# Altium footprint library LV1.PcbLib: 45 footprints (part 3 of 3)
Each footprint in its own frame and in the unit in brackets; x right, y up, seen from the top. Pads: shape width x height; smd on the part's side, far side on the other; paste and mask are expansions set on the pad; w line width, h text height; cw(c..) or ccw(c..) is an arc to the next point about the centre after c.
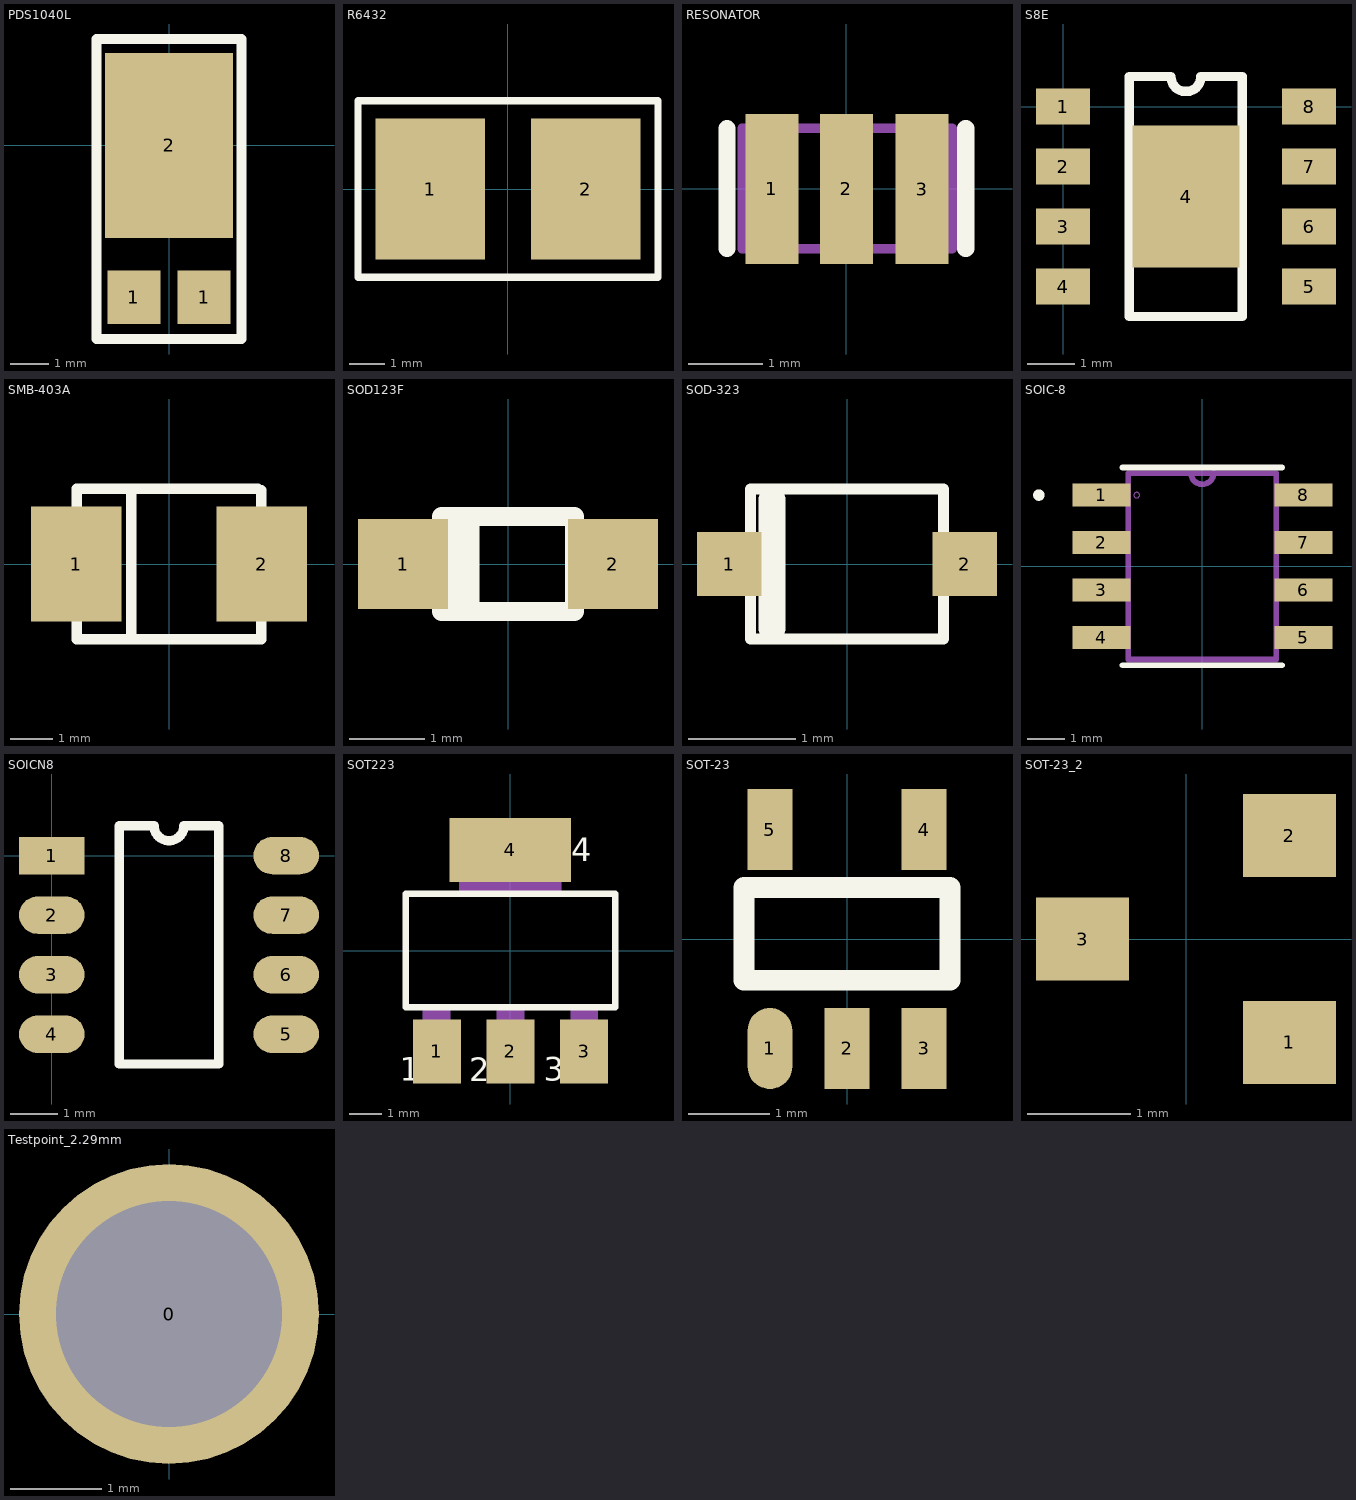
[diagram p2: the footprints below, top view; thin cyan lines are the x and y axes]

## PDS1040L [mm]
height 7.12
pads (3):
  rect 1.39x1.4 smd: 1(-0.92,-3.982) 1(0.92,-3.982)
  rect 3.36x4.86 smd: 2(0,0)
Top Overlay:
  lines w0.254: -1.905,-5.08 1.905,-5.08 1.905,2.794 -1.905,2.794 -1.905,-5.08
3D body: height 0.1, standoff 0, extent -1.397,0.762 1.397,2.286
3D body: height 0.1, standoff 0, extent -1.397,-4.064 -0.381,-2.032
3D body: height 0.1, standoff 0, extent 0.381,-4.064 1.397,-2.032
3D body: height 1, standoff 0, extent -1.524,-3.429 1.524,1.524

## R6432 [mm]
height 7.12
pads (2):
  rect 3.1x4 smd: 1(-2.2,0) 2(2.2,0)
Top Overlay:
  lines w0.2: -4.25,-2.5 -4.25,0 -4.25,2.5 4.25,2.5 4.25,-2.5 -4.25,-2.5

## RESONATOR [mil]
height 338.58
pads (3):
  rect 28x79 smd: 1(-39.37,0) 2(0,0) 3(40,0)
Top Overlay:
  lines w9: -62.99,-31.5 -62.99,32 ; 63,-31.5 63,32
Mechanical 16:
  lines w5: -55.12,-31.5 -55.12,32 56,32 56,-31.5 -55.12,-31.5

## S8E [mil]
height 338.58
pads (9):
  rect 45x30 smd: 1(0,0) 2(0,-50) 3(0,-100) 4(0,-150) 5(205,-150) 6(205,-100) 7(205,-50) 8(205,0)
  rect 89x118 smd: 4(102.5,-75)
Top Overlay:
  lines w7.87: 55.37,-175 149.47,-175 149.47,25 114.92,25 cw(c102.42,25) 89.92,25 55.37,25 55.37,-175

## SMB-403A [mil]
pads (2):
  rect 85x107.99 smd: 1(-87.01,0) 2(87.01,0)
Top Overlay:
  lines w10: -86.61,-70.87 -86.61,69.29 ; -86.61,70.87 83.46,70.87 ; -83.46,-70.87 86.61,-70.87 86.61,69.29 ; -35.43,-70.87 -35.43,70.87
3D body: height 78.74, standoff 0, extent -82.68,-74.8 90.55,66.93

## SOD123F [mm]
height 7.12
pads (2):
  rect 1.2x1.2 smd: 1(-1.4,0) 2(1.4,0)
Top Overlay:
  rectangle: -1.016,-0.635 -0.381,0.635
  lines w0.254: -0.889,-0.635 0.889,-0.635 0.889,0.635 -0.889,0.635

## SOD-323 [mm]
pads (2):
  rect 0.6x0.6 smd: 1(-1.1,0) 2(1.1,0)
Top Overlay:
  lines w0.1: -0.9,-0.7 0.9,-0.7 0.9,0.7 -0.9,0.7 -0.9,-0.7
  lines w0.254: -0.7,-0.6 -0.7,0.6

## SOIC-8 [mil]
pads (8):
  rect 61x24 smd paste-1000 mask-1000: 1(-106.3,75) 2(-106.3,25) 3(-106.3,-25) 4(-106.3,-75) 5(106.3,-75) 6(106.3,-25) 7(106.3,25) 8(106.3,75)
Top Overlay:
  lines w6: -84,-104 84,-104 ; -84,104 84,104 ; -175,75 ccw(c-172,75) -169,75 ccw(c-172,75) -175,75
Top Paste:
  region: -136.8,63 -75.8,63 -75.8,87 -136.8,87
  region: -136.8,13 -75.8,13 -75.8,37 -136.8,37
  region: -136.8,-37 -75.8,-37 -75.8,-13 -136.8,-13
  region: -136.8,-87 -75.8,-87 -75.8,-63 -136.8,-63
  region: 75.8,-87 136.8,-87 136.8,-63 75.8,-63
  region: 75.8,-37 136.8,-37 136.8,-13 75.8,-13
  region: 75.8,13 136.8,13 136.8,37 75.8,37
  region: 75.8,63 136.8,63 136.8,87 75.8,87
Top Solder:
  region: -140.74,59.06 -71.86,59.06 -71.86,90.94 -140.74,90.94
  region: -140.74,9.06 -71.86,9.06 -71.86,40.94 -140.74,40.94
  region: -140.74,-40.94 -71.86,-40.94 -71.86,-9.06 -140.74,-9.06
  region: -140.74,-90.94 -71.86,-90.94 -71.86,-59.06 -140.74,-59.06
  region: 71.86,-90.94 140.74,-90.94 140.74,-59.06 71.86,-59.06
  region: 71.86,-40.94 140.74,-40.94 140.74,-9.06 71.86,-9.06
  region: 71.86,9.06 140.74,9.06 140.74,40.94 71.86,40.94
  region: 71.86,59.06 140.74,59.06 140.74,90.94 71.86,90.94
Mechanical 1:
  lines w0: -72,75 ccw(c-69,75) -66,75 ccw(c-69,75) -72,75
  lines w6: -12,98.08 ccw(c0,98.5) 12,98.92 ; -78,-98 78,-98 78,98 -12,98 -78,98 -78,-98

## SOICN8 [mm]
pads (8):
  rect 1.4x0.8 smd: 1(0,0)
  oval 1.4x0.8 smd: 2(0,-1.27) 3(0,-2.54) 4(0,-3.81) 5(5,-3.81) 6(5,-2.54) 7(5,-1.27) 8(5,0)
Top Overlay:
  lines w0.2: 1.435,-4.445 3.565,-4.445 3.565,0.635 2.818,0.635 cw(c2.5,0.635) 2.183,0.635 1.435,0.635 1.435,-4.445
3D body: height 0.5, standoff 0, extent 4.318,-0.254 5.461,0.254
3D body: height 0.5, standoff 0, extent 4.318,-1.524 5.461,-1.016
3D body: height 0.5, standoff 0, extent 4.318,-2.794 5.461,-2.286
3D body: height 0.5, standoff 0, extent 4.318,-4.064 5.461,-3.556
3D body: height 0.5, standoff 0, extent -0.381,-4.064 0.762,-3.556
3D body: height 0.5, standoff 0, extent -0.381,-2.794 0.762,-2.286
3D body: height 0.5, standoff 0, extent -0.381,-1.524 0.762,-1.016
3D body: height 0.5, standoff 0, extent -0.381,-0.254 0.762,0.254
3D body: height 1, standoff 0, extent 0.762,-4.699 4.318,0.889

## SOT223 [mm]
height 8.6
pads (4):
  rect 1.5x2 smd: 1(-2.3,-3.15) 2(0,-3.15) 3(2.3,-3.15)
  rect 3.8x2 smd: 4(0,3.15)
Top Overlay:
  lines w0.203: -3.277,-1.778 -3.277,1.778 3.277,1.778 3.277,-1.778 -3.277,-1.778
  text "2" at -1.291,-4.327 h1.26
  text "1" at -3.453,-4.318 h1.26
  text "4" at 1.905,2.54 h1.26
  text "3" at 1.041,-4.318 h1.26
Mechanical 16:
  rectangle: 1.88,-3.658 2.743,-1.803
  rectangle: -2.743,-3.658 -1.88,-1.803
  rectangle: -0.432,-3.658 0.432,-1.803
  rectangle: -1.6,1.803 1.6,3.658
  rectangle: 1.88,-3.658 2.743,-1.803
  rectangle: -2.743,-3.658 -1.88,-1.803
  rectangle: -0.432,-3.658 0.432,-1.803
  rectangle: -1.6,1.803 1.6,3.658
3D body: height 0.1, standoff 0, extent -1.9,2.1 1.9,4.2
3D body: height 0.1, standoff 0, extent -3.1,-4.2 -1.5,-2.1
3D body: height 0.1, standoff 0, extent -0.8,-4.2 0.8,-2.1
3D body: height 0.1, standoff 0, extent 1.5,-4.2 3.1,-2.1
3D body: height 1, standoff 0, extent -3.3,-2.1 3.3,2.2

## SOT-23 [mm]
height 8.6
pads (5):
  oval 0.55x1 smd: 1(-0.95,-1.35)
  rect 0.55x1 smd: 2(0,-1.35) 3(0.95,-1.35) 4(0.95,1.35) 5(-0.95,1.35)
Top Overlay:
  lines w0.254: -1.27,-0.508 -1.27,0.635 1.27,0.635 1.27,-0.508 -1.27,-0.508

## SOT-23_2 [mm]
pads (3):
  rect 0.9x0.8 smd: 1(1,-1) 2(1,1) 3(-1,0)
3D body: height 0.5, standoff 0, extent -0.889,-1.016 1.016,1.143

## Testpoint_2.29mm [mm]
pads (1):
  round 3.3 hole 2.49: 0(0,0)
